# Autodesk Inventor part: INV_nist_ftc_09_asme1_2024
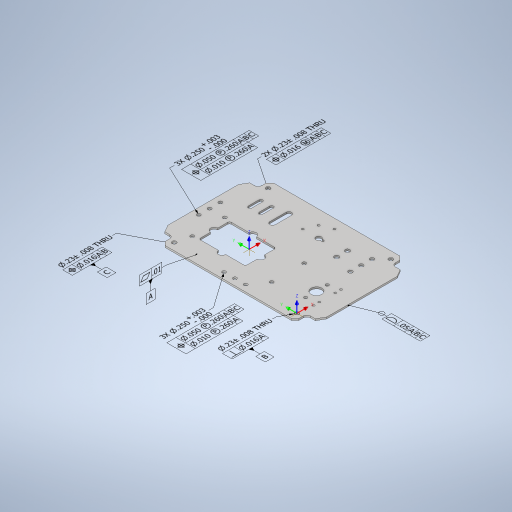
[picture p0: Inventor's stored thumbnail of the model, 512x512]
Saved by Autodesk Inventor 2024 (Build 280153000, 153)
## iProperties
Created: 2016-11
Part Number: INV_nist_ftc_09_asme1_2024
Material: Generic
Document SubType Name: Sheet Metal
Designer: t_liuje
Density: 1 g/cm^3
Sheet Metal Rule: Default
Appearance: Default
Author: t_liuje
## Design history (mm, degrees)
node "Face1"
  sketch "Sketch1" dims "d82" = 25.4
    geometry: L1 (139.7, -95.25)-(-139.7, -95.25); L2 (-139.7, -95.25)-(-139.7, 95.25); L3 (-139.7, 95.25)-(139.7, 95.25); L4 (139.7, 95.25)-(139.7, -95.25); L5 (182.898, 0)-(-210.589, 0); L6 (0, 76.018)-(0, -155.152); L7 (92.075, -57.15)-(92.075, -38.1); L8 (98.425, -38.1)-(98.425, -57.15); L9 (79.375, -38.1)-(79.375, -57.15); L10 (73.025, -57.15)-(73.025, -38.1); L11 (84.7, 28.651)-(19.05, 28.651); L12 (50.597, 12.848)-(50.597, 53.975); L13 (-12.7, -50.8)-(-20.32, -50.8); L14 (-20.32, -52.578)-(-17.118, -52.578); L15 (-20.32, -49.022)-(-17.118, -49.022); L16 (46.038, -61.9)-(46.038, -33.325); L17 (55.563, -33.325)-(55.563, -61.9); L18 (9.601, 1.651)-(44.247, 1.651); L19 (56.947, 1.651)-(91.592, 1.651); L20 (91.592, 1.651)-(91.592, 22.301); L21 (91.592, 35.001)-(91.592, 55.651); L22 (9.601, 55.651)-(9.601, 35.001); L23 (9.601, 22.301)-(9.601, 1.651); L24 (91.592, 55.651)-(56.947, 55.651); L25 (44.247, 55.651)-(9.601, 55.651); C1 r 3.175 at (101.6, 0); C2 r 3.175 at (128.27, -19.05); C3 r 3.175 at (128.27, 0); C4 r 3.175 at (128.27, 19.05); C5 r 3.175 at (101.6, 57.15); C6 r 3.175 at (-38.1, 0); C7 r 3.175 at (-38.1, 57.15); C8 r 3.175 at (0, 83.82); C9 r 3.175 at (19.05, 83.82); C10 r 3.175 at (-19.05, 83.82); C11 r 9.525 at (-91.44, 31.75); C12 r 2.807 at (-91.44, 50.8); C13 r 2.807 at (-91.44, 12.7); C14 r 1.981 at (-110.49, 17.78); C15 r 1.981 at (-110.49, 7.62); C16 r 1.981 at (-110.49, 45.72); C17 r 1.981 at (-110.49, 55.88); C18 r 4 at (-57.15, -57.15); C19 r 3.569 at (-91.44, -66.04); C20 r 4 at (-57.15, -38.1); C21 r 3.569 at (-91.44, -46.99); C22 r 3.569 at (-91.44, -27.94); C23 r 1.981 at (7.061, -70.561); C24 r 1.981 at (-12.7, -78.74); C25 r 1.981 at (15.24, -50.8); A1 r 3.175 centre (95.25, -57.15) between (92.075, -57.15) and (98.425, -57.15); A2 r 3.175 centre (95.25, -38.1) between (98.425, -38.1) and (92.075, -38.1); A3 r 3.175 centre (76.2, -57.15) between (73.025, -57.15) and (79.375, -57.15); A4 r 3.175 centre (76.2, -38.1) between (79.375, -38.1) and (73.025, -38.1); A5 r 4.763 centre (-12.7, -50.8) between (-17.118, -52.578) and (-17.118, -49.022); A6 r 1.778 centre (-20.32, -50.8) between (-20.32, -49.022) and (-20.32, -52.578); A7 r 4.763 centre (50.8, -61.9) between (46.038, -61.9) and (55.563, -61.9); A8 r 4.763 centre (50.8, -33.325) between (55.563, -33.325) and (46.038, -33.325); A9 r 6.35 centre (50.597, 1.651) between (44.247, 1.651) and (56.947, 1.651); A10 r 6.35 centre (9.601, 28.651) between (9.601, 35.001) and (9.601, 22.301); A11 r 6.35 centre (91.592, 28.651) between (91.592, 22.301) and (91.592, 35.001); A12 r 6.35 centre (50.597, 55.651) between (56.947, 55.651) and (44.247, 55.651); 1 further point
    constraints: 50 end point, 37 centre point, 24 point on circle, 14 point on line, 13 parallel, 12 tangent, 7 horizontal, 6 vertical, 5 perpendicular, 4 collinear, 1 equal radius, 9 other
    dimensions: "d0" = 279.4 distance of L2.end L3.end; "d1" = 190.5 distance of L1.end L2.end; "d4" = 44.45 distance from line of L4 A1.centre; "d5" = 38.1 distance from line of L1 A1.centre; "d6" = 6.35 distance between parallel lines of L8 L7; "d7" = 19.05 distance of A2.centre A1.centre; "d8" = 6.35 distance between parallel lines of L9 L10; "d9" = 19.05 distance of A4.centre A3.centre; "d10" = 19.05 distance of A1.centre A3.centre; "d11" = 38.1 distance from line of A3.centre L1; "d12" = 6.35 diameter of C1; "d13" = 38.1 distance from line of L4 C1.centre; "d14" = 6.35 diameter of C2; "d15" = 6.35 diameter of C3; "d16" = 6.35 diameter of C4; "d17" = 11.43 distance from line of L4 C2.centre (= d18); "d18" = 11.43 distance from line of L4 C3.centre; "d19" = 11.43 distance from line of L4 C4.centre (= d18); "d20" = 19.05 distance of C2.centre C3.centre; "d21" = 19.05 distance of C4.centre C3.centre (= d20); "d22" = 6.35 diameter of C5; "d23" = 38.1 distance from line of L4 C5.centre; "d24" = 38.1 distance from line of L3 C5.centre; "d25" = 6.35 diameter of C6; "d26" = 6.35 diameter of C7; "d27" = 101.6 distance from line of L2 C6.centre; "d28" = 101.6 distance from line of L2 C7.centre; "d29" = 38.1 distance from line of L3 C7.centre; "d30" = 6.35 diameter of C8; "d31" = 6.35 diameter of C9; "d32" = 6.35 diameter of C10; "d33" = 11.43 distance from line of L3 C8.centre; "d34" = 11.43 distance from line of L3 C9.centre (= d33); "d35" = 11.43 distance from line of L3 C10.centre (= d33); "d36" = 19.05 distance of C8.centre C10.centre; "d37" = 19.05 distance of C9.centre C8.centre; "d38" = 81.9912 distance of L21.end L22.start; "d39" = 54.0004 distance of L19.end L21.end; "d40" = 66.5988 distance between parallel lines of L3 L11; "d41" = 89.1032 distance between parallel lines of L4 L12; "d42" = 19.05 diameter of C11; "d43" = 48.26 distance from line of L2 C11.centre; "d44" = 63.5 distance from line of L3 C11.centre; "d45" = 5.6134 diameter of C12; "d46" = 48.26 distance from line of L2 C12.centre; "d47" = 19.05 distance of C12.centre C11.centre; "d48" = 19.05 distance of C11.centre C13.centre (= d47); "d49" = 48.26 distance from line of L2 C13.centre; "d50" = 3.9624 diameter of C14; "d51" = 3.9624 diameter of C15; "d52" = 3.9624 diameter of C16; "d53" = 3.9624 diameter of C17; "d54" = 29.21 distance from line of L2 C15.centre; "d55" = 29.21 distance from line of L2 C14.centre (= d54); "d56" = 29.21 distance from line of L2 C16.centre (= d55); "d57" = 29.21 distance from line of L2 C17.centre (= d54); "d58" = 10.16 distance of C15.centre C14.centre; "d59" = 13.97 vertical distance of C11.centre C14.centre; "d60" = 13.97 vertical distance of C11.centre C16.centre (= d59); "d61" = 10.16 distance of C17.centre C16.centre (= d58); "d63" = 1.778 radius of A6; "d64" = 7.62 distance of L13.start L13.end; "d65" = 3.556 distance between parallel lines of L15 L14; "d66" = 127 distance from line of L2 L13.start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
feature "Corner Round1" dims "d151" = 3.175
sketch "Sketch6"
  geometry: L1 (-139.7, 95.25)-(139.7, 95.25) reference; L2 (-139.7, -95.25)-(-139.7, 95.25) reference; 1 further point
  dimensions: "d110" = 12.7 distance from line of L1 point (-107.95, 82.55); "d111" = 31.75 distance from line of L2 point (-107.95, 82.55)
hole "Hole1" sketch "Sketch6" diameter "d112" = 5.9436; stored, may be unused: countersink angle "d116" = 82 deg, drill point angle "d118" = 0 deg; dims "d113" = 19.05, "d114" = 9.525, "d115" = 6.35, "d117" = 12.7
sketch "Sketch2"
  geometry: L1 (-139.7, 95.25)-(-117.475, 95.25); L2 (-117.475, 95.25)-(-117.475, 80.95); L3 (-123.825, 74.6)-(-139.7, 74.6); L4 (-139.7, 74.6)-(-139.7, 95.25); A1 r 6.35 centre (-123.825, 80.95) between (-123.825, 74.6) and (-117.475, 80.95); 2 further points
  constraints: 8 end point, 2 parallel, 2 point on circle, 2 point on line, 2 tangent, 1 centre point, 1 horizontal, 1 perpendicular
  dimensions: "d140" = 22.225 distance of point (-117.475, 74.6) L3.end; "d141" = 20.6502 distance of L1.end point (-117.475, 74.6); "d142" = 6.35 radius of A1
extrude "Extrusion1" cut sketch "Sketch2" stored distance "d143" = 25.4; taper "d144" = 0 deg
mirror "Mirror1"
mirror "Mirror2"
chamfer "Chamfer1" distance "d119" = 0.762; stored, may be unused: second distance "d120" = 3.175, angle "d121" = 45 deg
feature "Corner Chamfer1" dims "d145" = 6.35, "d146" = 6.35, angle "d147" = 45 deg
chamfer "Chamfer2" distance "d152" = 12.7; stored, may be unused: second distance "d153" = 7.3406, angle "d154" = 45 deg
chamfer "Chamfer3" distance "d155" = 12.7; stored, may be unused: second distance "d156" = 7.3406, angle "d157" = 45 deg
feature "Corner Chamfer3" dims "d158" = 12.7, "d159" = 7.3406, angle "d160" = 45 deg
feature "Corner Chamfer4" dims "d161" = 12.7, "d162" = 7.3406, angle "d163" = 45 deg
sketch "Sketch3" dims "d14" = 6.35
  geometry: L1 (-21.886, 73.182)-(-21.886, 84.689); L2 (-21.886, 84.689)-(-8.077, 84.689); L3 (-8.077, 84.689)-(-8.077, 73.182); L4 (-8.077, 73.182)-(-21.886, 73.182); A1 r 38.1 centre (12.7, 50.8) between (-22.5, 65.38) and (-1.88, 86); 1 further point
  constraints: 2 point on circle, 1 centre point, 1 coincident, 2 other
sketch "Sketch4" dims "d14" = 6.35
  geometry: L1 (-18.416, 50.823)-(-12.066, 50.823); L2 (12.7, 82.108)-(12.7, 75.758); L3 (-4.811, 68.314)-(-9.304, 72.802); A1 r 27.924 centre (12.684, 50.816) between (-4.326, 72.961) and (-9.591, 67.655); 1 further point
  constraints: 6 end point, 3 point on circle, 1 centre point, 1 horizontal, 1 point on line, 1 vertical
sketch "Sketch5"
  geometry: L1 (97.882, 66.04)-(85.182, 66.04); L2 (91.532, 59.936)-(91.532, 72.636); 1 further point
  constraints: 4 end point, 1 horizontal, 1 point on line, 1 vertical
body "Solid1"
node "Annotations"
node "Tolerance Features"
face "Plate1" dims "d164" = 3.048 (derived)
node "Planar Surface 1" dims "d165" = 9.29719 (derived), "d166" = 2.506 (derived), "d167" = 0.254 (derived), "d168" = 0 (derived), "d169" = 0 (derived), "d201" = -23.8064 (derived), "d202" = 19.05 (derived), "d203" = 1.27 (derived), "d204" = 0 (derived), "d205" = 0 (derived), "d206" = 0.254 (derived), "d207" = 0 (derived), "d208" = 0 (derived), "d240" = 20.67597 (derived), "d241" = 9.525 (derived), "d242" = 1.016 (derived), "d243" = 0 (derived), "d244" = 0 (derived), "d245" = 0.254 (derived), "d246" = 0 (derived), "d247" = 0 (derived), "d468" = -26.99719 (derived), "d469" = 10 (derived), "d470" = 5 (derived)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
node "Feature Control Frame 1"
node "Datum Identifier 1" dims "d12" = 6.35, "d165" = 9.29719 (derived), "d166" = 2.506 (derived), "d167" = 0.254 (derived), "d168" = 0 (derived), "d169" = 0 (derived), "d201" = -23.8064 (derived), "d202" = 19.05 (derived), "d203" = 1.27 (derived), "d204" = 0 (derived), "d205" = 0 (derived), "d206" = 0.254 (derived), "d207" = 0 (derived), "d208" = 0 (derived), "d240" = 20.67597 (derived), "d241" = 9.525 (derived), "d242" = 1.016 (derived), "d243" = 0 (derived), "d244" = 0 (derived), "d245" = 0.254 (derived), "d246" = 0 (derived), "d247" = 0 (derived), "d468" = -26.99719 (derived), "d469" = 10 (derived)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
node "Datum Reference Frame 1"
node "Simple Hole 1" dims "d165" = 9.29719 (derived), "d166" = 2.506 (derived), "d167" = 0.254 (derived), "d168" = 0 (derived), "d169" = 0 (derived), "d201" = -23.8064 (derived), "d202" = 19.05 (derived), "d203" = 1.27 (derived), "d204" = 0 (derived), "d205" = 0 (derived), "d206" = 0.254 (derived), "d207" = 0 (derived), "d208" = 0 (derived), "d240" = 20.67597 (derived), "d241" = 9.525 (derived), "d242" = 1.016 (derived), "d243" = 0 (derived), "d244" = 0 (derived), "d245" = 0.254 (derived), "d246" = 0 (derived), "d247" = 0 (derived), "d468" = -26.99719 (derived), "d469" = 10 (derived), "d470" = 5 (derived)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
node "Datum Reference Frame 2"
node "Simple Hole 2" dims "d165" = 9.29719 (derived), "d166" = 2.506 (derived), "d167" = 0.254 (derived), "d168" = 0 (derived), "d169" = 0 (derived), "d201" = -23.8064 (derived), "d202" = 19.05 (derived), "d203" = 1.27 (derived), "d204" = 0 (derived), "d205" = 0 (derived), "d206" = 0.254 (derived), "d207" = 0 (derived), "d208" = 0 (derived), "d240" = 20.67597 (derived), "d241" = 9.525 (derived), "d242" = 1.016 (derived), "d243" = 0 (derived), "d244" = 0 (derived), "d245" = 0.254 (derived), "d246" = 0 (derived), "d247" = 0 (derived), "d468" = -26.99719 (derived), "d469" = 10 (derived), "d470" = 5 (derived)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
node "Datum Reference Frame 3"
node "Parallel Axes Pattern 1"
node "Simple Hole 7" dims "d165" = 9.29719 (derived), "d166" = 2.506 (derived), "d167" = 0.254 (derived), "d168" = 0 (derived), "d169" = 0 (derived), "d201" = -23.8064 (derived), "d202" = 19.05 (derived), "d203" = 1.27 (derived), "d204" = 0 (derived), "d205" = 0 (derived), "d206" = 0.254 (derived), "d207" = 0 (derived), "d208" = 0 (derived), "d240" = 20.67597 (derived), "d241" = 9.525 (derived), "d242" = 1.016 (derived), "d243" = 0 (derived), "d244" = 0 (derived), "d245" = 0.254 (derived), "d246" = 0 (derived), "d247" = 0 (derived), "d468" = -26.99719 (derived), "d469" = 10 (derived), "d470" = 5 (derived)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
node "Diameter Dimension 3" dims "d0" = 279.4, "d1" = 190.5, "d4" = 44.45, "d5" = 38.1, "d6" = 6.35, "d7" = 19.05, "d8" = 6.35, "d9" = 19.05, "d10" = 19.05, "d11" = 38.1, "d12" = 6.35, "d13" = 38.1, "d14" = 6.35, "d15" = 6.35, "d16" = 6.35, "d17" = 11.43 (= d18), "d18" = 11.43, "d19" = 11.43 (= d18), "d20" = 19.05, "d21" = 19.05 (= d20), "d22" = 6.35, "d23" = 38.1, "d24" = 38.1, "d25" = 6.35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
node "Feature Control Frame 8"
node "Datum Identifier 4" dims "d12" = 6.35, "d165" = 9.29719 (derived), "d166" = 2.506 (derived), "d167" = 0.254 (derived), "d168" = 0 (derived), "d169" = 0 (derived), "d201" = -23.8064 (derived), "d202" = 19.05 (derived), "d203" = 1.27 (derived), "d204" = 0 (derived), "d205" = 0 (derived), "d206" = 0.254 (derived), "d207" = 0 (derived), "d208" = 0 (derived), "d240" = 20.67597 (derived), "d241" = 9.525 (derived), "d242" = 1.016 (derived), "d243" = 0 (derived), "d244" = 0 (derived), "d245" = 0.254 (derived), "d246" = 0 (derived), "d247" = 0 (derived), "d468" = -26.99719 (derived), "d469" = 10 (derived)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
node "Datum Reference Frame 4"
node "Parallel Axes Pattern 3"
node "Parallel Axes Pattern 4"
node "Simple Hole 16" dims "d165" = 9.29719 (derived), "d166" = 2.506 (derived), "d167" = 0.254 (derived), "d168" = 0 (derived), "d169" = 0 (derived), "d201" = -23.8064 (derived), "d202" = 19.05 (derived), "d203" = 1.27 (derived), "d204" = 0 (derived), "d205" = 0 (derived), "d206" = 0.254 (derived), "d207" = 0 (derived), "d208" = 0 (derived), "d240" = 20.67597 (derived), "d241" = 9.525 (derived), "d242" = 1.016 (derived), "d243" = 0 (derived), "d244" = 0 (derived), "d245" = 0.254 (derived), "d246" = 0 (derived), "d247" = 0 (derived), "d468" = -26.99719 (derived), "d469" = 10 (derived), "d470" = 5 (derived)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
node "Diameter Dimension 8" dims "d0" = 279.4, "d1" = 190.5, "d4" = 44.45, "d5" = 38.1, "d6" = 6.35, "d7" = 19.05, "d8" = 6.35, "d9" = 19.05, "d10" = 19.05, "d11" = 38.1, "d12" = 6.35, "d13" = 38.1, "d14" = 6.35, "d15" = 6.35, "d16" = 6.35, "d17" = 11.43 (= d18), "d18" = 11.43, "d19" = 11.43 (= d18), "d20" = 19.05, "d21" = 19.05 (= d20), "d22" = 6.35, "d23" = 38.1, "d24" = 38.1, "d25" = 6.35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
node "Feature Control Frame 13"
node "Datum Identifier 7" dims "d12" = 6.35, "d165" = 9.29719 (derived), "d166" = 2.506 (derived), "d167" = 0.254 (derived), "d168" = 0 (derived), "d169" = 0 (derived), "d201" = -23.8064 (derived), "d202" = 19.05 (derived), "d203" = 1.27 (derived), "d204" = 0 (derived), "d205" = 0 (derived), "d206" = 0.254 (derived), "d207" = 0 (derived), "d208" = 0 (derived), "d240" = 20.67597 (derived), "d241" = 9.525 (derived), "d242" = 1.016 (derived), "d243" = 0 (derived), "d244" = 0 (derived), "d245" = 0.254 (derived), "d246" = 0 (derived), "d247" = 0 (derived), "d468" = -26.99719 (derived), "d469" = 10 (derived)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
node "Datum Reference Frame 7"
node "General Note 1"
node "Slotted Hole 1"
node "Slotted Hole 2"
node "Extruded Group 1"
node "Simple Hole 28"
node "Simple Hole 29"
node "Simple Hole 30"
node "Parallel Axes Pattern 5"
node "Diameter Dimension 17" dims "d0" = 279.4, "d1" = 190.5, "d4" = 44.45, "d5" = 38.1, "d6" = 6.35, "d7" = 19.05, "d8" = 6.35, "d9" = 19.05, "d10" = 19.05, "d11" = 38.1, "d12" = 6.35, "d13" = 38.1, "d14" = 6.35, "d15" = 6.35, "d16" = 6.35, "d17" = 11.43 (= d18), "d18" = 11.43, "d19" = 11.43 (= d18), "d20" = 19.05, "d21" = 19.05 (= d20), "d22" = 6.35, "d23" = 38.1, "d24" = 38.1, "d25" = 6.35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
node "Feature Control Frame 31"
node "Simple Hole 31"
node "Simple Hole 32"
node "Simple Hole 33"
node "Parallel Axes Pattern 6"
node "Diameter Dimension 18" dims "d0" = 279.4, "d1" = 190.5, "d4" = 44.45, "d5" = 38.1, "d6" = 6.35, "d7" = 19.05, "d8" = 6.35, "d9" = 19.05, "d10" = 19.05, "d11" = 38.1, "d12" = 6.35, "d13" = 38.1, "d14" = 6.35, "d15" = 6.35, "d16" = 6.35, "d17" = 11.43 (= d18), "d18" = 11.43, "d19" = 11.43 (= d18), "d20" = 19.05, "d21" = 19.05 (= d20), "d22" = 6.35, "d23" = 38.1, "d24" = 38.1, "d25" = 6.35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
node "Feature Control Frame 32"
node "Parallel Axes Pattern 7" dims "d165" = 9.29719 (derived), "d166" = 2.506 (derived), "d167" = 0.254 (derived), "d168" = 0 (derived), "d169" = 0 (derived), "d201" = -23.8064 (derived), "d202" = 19.05 (derived), "d203" = 1.27 (derived), "d204" = 0 (derived), "d205" = 0 (derived), "d206" = 0.254 (derived), "d207" = 0 (derived), "d208" = 0 (derived), "d240" = 20.67597 (derived), "d241" = 9.525 (derived), "d242" = 1.016 (derived), "d243" = 0 (derived), "d244" = 0 (derived), "d245" = 0.254 (derived), "d246" = 0 (derived), "d247" = 0 (derived), "d468" = -26.99719 (derived), "d469" = 10 (derived), "d470" = 5 (derived)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
node "Datum Reference Frame 11"
node "Datum Reference Frame 12"
node "Datum Reference Frame 13"
node "Planar Surface 30"
node "Planar Surface 31"
node "Slot 6" dims "d165" = 9.29719 (derived), "d166" = 2.506 (derived), "d167" = 0.254 (derived), "d168" = 0 (derived), "d169" = 0 (derived), "d201" = -23.8064 (derived), "d202" = 19.05 (derived), "d203" = 1.27 (derived), "d204" = 0 (derived), "d205" = 0 (derived), "d206" = 0.254 (derived), "d207" = 0 (derived), "d208" = 0 (derived), "d240" = 20.67597 (derived), "d241" = 9.525 (derived), "d242" = 1.016 (derived), "d243" = 0 (derived), "d244" = 0 (derived), "d245" = 0.254 (derived), "d246" = 0 (derived), "d247" = 0 (derived), "d468" = -26.99719 (derived), "d469" = 10 (derived), "d470" = 5 (derived)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
node "Linear Dimension 10" dims "d0" = 279.4, "d1" = 190.5, "d4" = 44.45, "d5" = 38.1, "d6" = 6.35, "d7" = 19.05, "d8" = 6.35, "d9" = 19.05, "d10" = 19.05, "d11" = 38.1, "d12" = 6.35, "d13" = 38.1, "d14" = 6.35, "d15" = 6.35, "d16" = 6.35, "d17" = 11.43 (= d18), "d18" = 11.43, "d19" = 11.43 (= d18), "d20" = 19.05, "d21" = 19.05 (= d20), "d22" = 6.35, "d23" = 38.1, "d24" = 38.1, "d25" = 6.35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
node "Feature Control Frame 38"
node "Datum Identifier 10" dims "d12" = 6.35, "d165" = 9.29719 (derived), "d166" = 2.506 (derived), "d167" = 0.254 (derived), "d168" = 0 (derived), "d169" = 0 (derived), "d201" = -23.8064 (derived), "d202" = 19.05 (derived), "d203" = 1.27 (derived), "d204" = 0 (derived), "d205" = 0 (derived), "d206" = 0.254 (derived), "d207" = 0 (derived), "d208" = 0 (derived), "d240" = 20.67597 (derived), "d241" = 9.525 (derived), "d242" = 1.016 (derived), "d243" = 0 (derived), "d244" = 0 (derived), "d245" = 0.254 (derived), "d246" = 0 (derived), "d247" = 0 (derived), "d468" = -26.99719 (derived), "d469" = 10 (derived)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
node "Datum Reference Frame 14"
node "Datum Reference Frame 15"
node "Parallel Axes Pattern 8"
node "Cylindrical Surface 27"
node "Feature Control Frame 41"
node "Datum Reference Frame 16"
node "Parallel Axes Pattern 9" dims "d165" = 9.29719 (derived), "d166" = 2.506 (derived), "d167" = 0.254 (derived), "d168" = 0 (derived), "d169" = 0 (derived), "d201" = -23.8064 (derived), "d202" = 19.05 (derived), "d203" = 1.27 (derived), "d204" = 0 (derived), "d205" = 0 (derived), "d206" = 0.254 (derived), "d207" = 0 (derived), "d208" = 0 (derived), "d240" = 20.67597 (derived), "d241" = 9.525 (derived), "d242" = 1.016 (derived), "d243" = 0 (derived), "d244" = 0 (derived), "d245" = 0.254 (derived), "d246" = 0 (derived), "d247" = 0 (derived), "d468" = -26.99719 (derived), "d469" = 10 (derived), "d470" = 5 (derived)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
node "Datum Reference Frame 17"
node "Datum Reference Frame 18"
node "Simple Hole 65"
node "Simple Hole 66"
node "Hole Note 5" dims "d0" = 279.4, "d1" = 190.5, "d4" = 44.45, "d5" = 38.1, "d6" = 6.35, "d7" = 19.05, "d8" = 6.35, "d9" = 19.05, "d10" = 19.05, "d11" = 38.1, "d12" = 6.35, "d13" = 38.1, "d14" = 6.35, "d15" = 6.35, "d16" = 6.35, "d17" = 11.43 (= d18), "d18" = 11.43, "d19" = 11.43 (= d18), "d20" = 19.05, "d21" = 19.05 (= d20), "d22" = 6.35, "d23" = 38.1, "d24" = 38.1, "d25" = 6.35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
node "Feature Control Frame 55"
node "Hole Note 1" dims "d0" = 279.4, "d1" = 190.5, "d4" = 44.45, "d5" = 38.1, "d6" = 6.35, "d7" = 19.05, "d8" = 6.35, "d9" = 19.05, "d10" = 19.05, "d11" = 38.1, "d12" = 6.35, "d13" = 38.1, "d14" = 6.35, "d15" = 6.35, "d16" = 6.35, "d17" = 11.43 (= d18), "d18" = 11.43, "d19" = 11.43 (= d18), "d20" = 19.05, "d21" = 19.05 (= d20), "d22" = 6.35, "d23" = 38.1, "d24" = 38.1, "d25" = 6.35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
node "Feature Control Frame 56"
node "Datum Identifier 12" dims "d12" = 6.35, "d165" = 9.29719 (derived), "d166" = 2.506 (derived), "d167" = 0.254 (derived), "d168" = 0 (derived), "d169" = 0 (derived), "d201" = -23.8064 (derived), "d202" = 19.05 (derived), "d203" = 1.27 (derived), "d204" = 0 (derived), "d205" = 0 (derived), "d206" = 0.254 (derived), "d207" = 0 (derived), "d208" = 0 (derived), "d240" = 20.67597 (derived), "d241" = 9.525 (derived), "d242" = 1.016 (derived), "d243" = 0 (derived), "d244" = 0 (derived), "d245" = 0.254 (derived), "d246" = 0 (derived), "d247" = 0 (derived), "d468" = -26.99719 (derived), "d469" = 10 (derived)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
node "Hole Note 2" dims "d0" = 279.4, "d1" = 190.5, "d4" = 44.45, "d5" = 38.1, "d6" = 6.35, "d7" = 19.05, "d8" = 6.35, "d9" = 19.05, "d10" = 19.05, "d11" = 38.1, "d12" = 6.35, "d13" = 38.1, "d14" = 6.35, "d15" = 6.35, "d16" = 6.35, "d17" = 11.43 (= d18), "d18" = 11.43, "d19" = 11.43 (= d18), "d20" = 19.05, "d21" = 19.05 (= d20), "d22" = 6.35, "d23" = 38.1, "d24" = 38.1, "d25" = 6.35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
node "Feature Control Frame 57"
node "Datum Identifier 13" dims "d12" = 6.35, "d165" = 9.29719 (derived), "d166" = 2.506 (derived), "d167" = 0.254 (derived), "d168" = 0 (derived), "d169" = 0 (derived), "d201" = -23.8064 (derived), "d202" = 19.05 (derived), "d203" = 1.27 (derived), "d204" = 0 (derived), "d205" = 0 (derived), "d206" = 0.254 (derived), "d207" = 0 (derived), "d208" = 0 (derived), "d240" = 20.67597 (derived), "d241" = 9.525 (derived), "d242" = 1.016 (derived), "d243" = 0 (derived), "d244" = 0 (derived), "d245" = 0.254 (derived), "d246" = 0 (derived), "d247" = 0 (derived), "d468" = -26.99719 (derived), "d469" = 10 (derived)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
node "Cylindrical Surface 28"
node "Planar Surface 32"
node "Planar Surface 33"
node "Cylindrical Surface 29"
node "Planar Surface 34"
node "Cylindrical Surface 30"
node "Cylindrical Surface 31"
node "Planar Surface 35"
node "Cylindrical Surface 32"
node "Planar Surface 36"
node "Cylindrical Surface 33"
node "Planar Surface 37"
node "Cylindrical Surface 34"
node "Planar Surface 38"
node "Cylindrical Surface 35"
node "Planar Surface 39"
node "Feature Control Frame 59"
node "Simple Hole 71"
node "Simple Hole 72"
node "Simple Hole 73"
node "Diameter Dimension 35" dims "d0" = 279.4, "d1" = 190.5, "d4" = 44.45, "d5" = 38.1, "d6" = 6.35, "d7" = 19.05, "d8" = 6.35, "d9" = 19.05, "d10" = 19.05, "d11" = 38.1, "d12" = 6.35, "d13" = 38.1, "d14" = 6.35, "d15" = 6.35, "d16" = 6.35, "d17" = 11.43 (= d18), "d18" = 11.43, "d19" = 11.43 (= d18), "d20" = 19.05, "d21" = 19.05 (= d20), "d22" = 6.35, "d23" = 38.1, "d24" = 38.1, "d25" = 6.35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
node "Feature Control Frame 61"
node "Simple Hole 74"
node "Simple Hole 75"
node "Simple Hole 76"
node "Simple Hole 77"
node "Diameter Dimension 36" dims "d0" = 279.4, "d1" = 190.5, "d4" = 44.45, "d5" = 38.1, "d6" = 6.35, "d7" = 19.05, "d8" = 6.35, "d9" = 19.05, "d10" = 19.05, "d11" = 38.1, "d12" = 6.35, "d13" = 38.1, "d14" = 6.35, "d15" = 6.35, "d16" = 6.35, "d17" = 11.43 (= d18), "d18" = 11.43, "d19" = 11.43 (= d18), "d20" = 19.05, "d21" = 19.05 (= d20), "d22" = 6.35, "d23" = 38.1, "d24" = 38.1, "d25" = 6.35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
node "Feature Control Frame 62"
node "Datum Identifier 14" dims "d12" = 6.35, "d165" = 9.29719 (derived), "d166" = 2.506 (derived), "d167" = 0.254 (derived), "d168" = 0 (derived), "d169" = 0 (derived), "d201" = -23.8064 (derived), "d202" = 19.05 (derived), "d203" = 1.27 (derived), "d204" = 0 (derived), "d205" = 0 (derived), "d206" = 0.254 (derived), "d207" = 0 (derived), "d208" = 0 (derived), "d240" = 20.67597 (derived), "d241" = 9.525 (derived), "d242" = 1.016 (derived), "d243" = 0 (derived), "d244" = 0 (derived), "d245" = 0.254 (derived), "d246" = 0 (derived), "d247" = 0 (derived), "d468" = -26.99719 (derived), "d469" = 10 (derived)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
node "Simple Hole 83"
node "Simple Hole 84"
node "Diameter Dimension 39" dims "d0" = 279.4, "d1" = 190.5, "d4" = 44.45, "d5" = 38.1, "d6" = 6.35, "d7" = 19.05, "d8" = 6.35, "d9" = 19.05, "d10" = 19.05, "d11" = 38.1, "d12" = 6.35, "d13" = 38.1, "d14" = 6.35, "d15" = 6.35, "d16" = 6.35, "d17" = 11.43 (= d18), "d18" = 11.43, "d19" = 11.43 (= d18), "d20" = 19.05, "d21" = 19.05 (= d20), "d22" = 6.35, "d23" = 38.1, "d24" = 38.1, "d25" = 6.35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
node "Feature Control Frame 65"
node "Simple Hole 85"
node "Simple Hole 86"
node "Diameter Dimension 40" dims "d0" = 279.4, "d1" = 190.5, "d4" = 44.45, "d5" = 38.1, "d6" = 6.35, "d7" = 19.05, "d8" = 6.35, "d9" = 19.05, "d10" = 19.05, "d11" = 38.1, "d12" = 6.35, "d13" = 38.1, "d14" = 6.35, "d15" = 6.35, "d16" = 6.35, "d17" = 11.43 (= d18), "d18" = 11.43, "d19" = 11.43 (= d18), "d20" = 19.05, "d21" = 19.05 (= d20), "d22" = 6.35, "d23" = 38.1, "d24" = 38.1, "d25" = 6.35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
node "Feature Control Frame 66"
node "Datum Identifier 15" dims "d12" = 6.35, "d165" = 9.29719 (derived), "d166" = 2.506 (derived), "d167" = 0.254 (derived), "d168" = 0 (derived), "d169" = 0 (derived), "d201" = -23.8064 (derived), "d202" = 19.05 (derived), "d203" = 1.27 (derived), "d204" = 0 (derived), "d205" = 0 (derived), "d206" = 0.254 (derived), "d207" = 0 (derived), "d208" = 0 (derived), "d240" = 20.67597 (derived), "d241" = 9.525 (derived), "d242" = 1.016 (derived), "d243" = 0 (derived), "d244" = 0 (derived), "d245" = 0.254 (derived), "d246" = 0 (derived), "d247" = 0 (derived), "d468" = -26.99719 (derived), "d469" = 10 (derived)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
node "Extruded Group 2"
node "Planar Surface 42"
node "Planar Surface 43"
node "Planar Surface 44"
node "Cylindrical Surface 38"
node "Planar Surface 45"
node "Planar Surface 46"
node "Planar Surface 47"
node "Planar Surface 48"
node "Planar Surface 49"
node "Cylindrical Surface 39"
node "Planar Surface 50"
node "Planar Surface 51"
node "Planar Surface 52"
node "Planar Surface 53"
node "Planar Surface 54"
node "Cylindrical Surface 40"
node "Planar Surface 55"
node "Planar Surface 56"
node "Planar Surface 57"
node "Planar Surface 58"
node "Planar Surface 59"
node "Cylindrical Surface 41"
node "Planar Surface 60"
node "Planar Surface 61"
node "Feature Control Frame 67"
node "Planar Surface 62"
node "Planar Surface 63"
node "Slot 7"
node "Cylindrical Surface 42"
node "Cylindrical Surface 43"
node "Opposed Cylinders 4"
node "Linear Dimension 11" dims "d0" = 279.4, "d1" = 190.5, "d4" = 44.45, "d5" = 38.1, "d6" = 6.35, "d7" = 19.05, "d8" = 6.35, "d9" = 19.05, "d10" = 19.05, "d11" = 38.1, "d12" = 6.35, "d13" = 38.1, "d14" = 6.35, "d15" = 6.35, "d16" = 6.35, "d17" = 11.43 (= d18), "d18" = 11.43, "d19" = 11.43 (= d18), "d20" = 19.05, "d21" = 19.05 (= d20), "d22" = 6.35, "d23" = 38.1, "d24" = 38.1, "d25" = 6.35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
node "Feature Control Frame 68"
node "Leader Text 14"
node "Linear Dimension 4" dims "d0" = 279.4, "d1" = 190.5, "d4" = 44.45, "d5" = 38.1, "d6" = 6.35, "d7" = 19.05, "d8" = 6.35, "d9" = 19.05, "d10" = 19.05, "d11" = 38.1, "d12" = 6.35, "d13" = 38.1, "d14" = 6.35, "d15" = 6.35, "d16" = 6.35, "d17" = 11.43 (= d18), "d18" = 11.43, "d19" = 11.43 (= d18), "d20" = 19.05, "d21" = 19.05 (= d20), "d22" = 6.35, "d23" = 38.1, "d24" = 38.1, "d25" = 6.35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
node "Planar Surface 64"
node "Planar Surface 65"
node "Slot 8"
node "Cylindrical Surface 44"
node "Cylindrical Surface 45"
node "Opposed Cylinders 5"
node "Linear Dimension 13" dims "d0" = 279.4, "d1" = 190.5, "d4" = 44.45, "d5" = 38.1, "d6" = 6.35, "d7" = 19.05, "d8" = 6.35, "d9" = 19.05, "d10" = 19.05, "d11" = 38.1, "d12" = 6.35, "d13" = 38.1, "d14" = 6.35, "d15" = 6.35, "d16" = 6.35, "d17" = 11.43 (= d18), "d18" = 11.43, "d19" = 11.43 (= d18), "d20" = 19.05, "d21" = 19.05 (= d20), "d22" = 6.35, "d23" = 38.1, "d24" = 38.1, "d25" = 6.35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
node "Feature Control Frame 69"
node "Leader Text 15"
node "Linear Dimension 2" dims "d0" = 279.4, "d1" = 190.5, "d4" = 44.45, "d5" = 38.1, "d6" = 6.35, "d7" = 19.05, "d8" = 6.35, "d9" = 19.05, "d10" = 19.05, "d11" = 38.1, "d12" = 6.35, "d13" = 38.1, "d14" = 6.35, "d15" = 6.35, "d16" = 6.35, "d17" = 11.43 (= d18), "d18" = 11.43, "d19" = 11.43 (= d18), "d20" = 19.05, "d21" = 19.05 (= d20), "d22" = 6.35, "d23" = 38.1, "d24" = 38.1, "d25" = 6.35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
node "Feature Control Frame 70"
node "Leader Text 16"
node "Simple Hole 87"
node "Simple Hole 88"
node "Simple Hole 89"
node "Diameter Dimension 41" dims "d0" = 279.4, "d1" = 190.5, "d4" = 44.45, "d5" = 38.1, "d6" = 6.35, "d7" = 19.05, "d8" = 6.35, "d9" = 19.05, "d10" = 19.05, "d11" = 38.1, "d12" = 6.35, "d13" = 38.1, "d14" = 6.35, "d15" = 6.35, "d16" = 6.35, "d17" = 11.43 (= d18), "d18" = 11.43, "d19" = 11.43 (= d18), "d20" = 19.05, "d21" = 19.05 (= d20), "d22" = 6.35, "d23" = 38.1, "d24" = 38.1, "d25" = 6.35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
node "Feature Control Frame 71"
node "Simple Hole 90"
node "Simple Hole 91"
node "Simple Hole 92"
node "Simple Hole 93"
node "Parallel Axes Pattern 10"
node "Diameter Dimension 42" dims "d0" = 279.4, "d1" = 190.5, "d4" = 44.45, "d5" = 38.1, "d6" = 6.35, "d7" = 19.05, "d8" = 6.35, "d9" = 19.05, "d10" = 19.05, "d11" = 38.1, "d12" = 6.35, "d13" = 38.1, "d14" = 6.35, "d15" = 6.35, "d16" = 6.35, "d17" = 11.43 (= d18), "d18" = 11.43, "d19" = 11.43 (= d18), "d20" = 19.05, "d21" = 19.05 (= d20), "d22" = 6.35, "d23" = 38.1, "d24" = 38.1, "d25" = 6.35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
node "Feature Control Frame 72"
other parameters: "Thickness" = 3.048, "BendRadius" = 3.048 (= Thickness), "BendReliefWidth" = 3.048 (= Thickness), "BendReliefDepth" = 1.524 (= 0.5 x Thickness), "CornerReliefSize" = 12.192 (= 4 x Thickness), "SeamGap" = 0.00508, "MinimumRemnant" = 6.096 (= 2 x Thickness), "JacobiRadiusSize" = 3.048 (= BendRadius), "GapSize" = 3.048 (= Thickness), "d105" = 3.048 (= BendRadius), "d387" = 0, "d388" = 0, "d389" = 0, "d390" = 90 deg, "d391" = 0, "d392" = -90 deg, "d393" = 0, "d394" = 0, "d395" = 0, "d396" = 90 deg, "d397" = 0, "d398" = -90 deg, "d399" = 0, "d400" = 0, "d401" = 0, "d402" = 90 deg, "d403" = 0, "d404" = -90 deg, "d405" = 12.7, "d406" = 0, "d407" = 25.4, "d408" = 90 deg, "d409" = 0, "d410" = -90 deg
